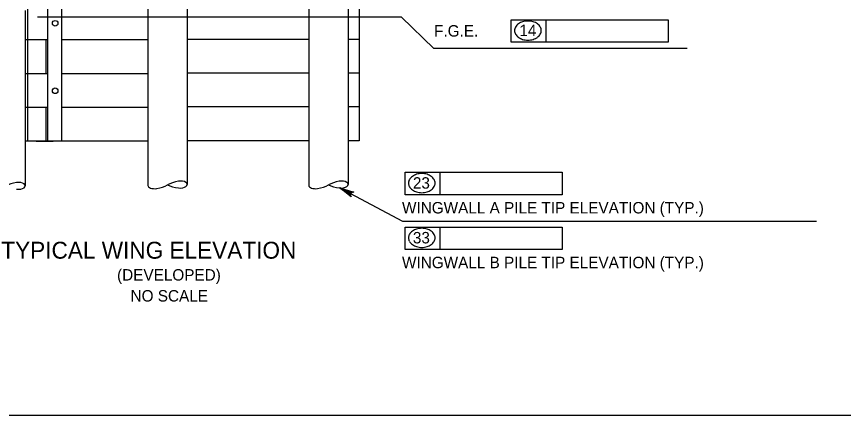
# Model space of a CAD drawing. Extents: x 638304 to 640306, y 296653 to 298435.
# Drawn here: x 638840 to 639056.8, y 297262.5 to 297367 of the extents above; entities that cross this region are included whole.
import ezdxf

# ---------------------------------------------------------------- set-up
doc = ezdxf.new("R2010")
doc.units = 0
for name, color, linetype in [('2', 7, 'Continuous'), ('5', 7, 'Continuous'), ('Level 4', 7, 'Continuous'), ('Level 5', 7, 'Continuous')]:
    doc.layers.add(name, color=color, linetype=linetype)

msp = doc.modelspace()

# ---------------------------------------------------------------- linework, layer by layer
at = {"layer": '2'}
msp.add_line((639261.46, 297262.46), (638475.46, 297262.46), dxfattribs=at)
at = {"layer": 'Level 4'}
for p, q in [((638842.93, 297413.92), (638842.93, 297334.35)), ((638926.95, 297395.53), (638926.95, 297323.03)), ((638929.9, 297396.36), (638929.9, 297334.47)), ((638916.63, 297392.09), (638916.63, 297322.76)), ((638884.77, 297381.85), (638884.77, 297323.03)), ((638874.45, 297377.11), (638874.45, 297322.76)), ((638851.9, 297334.35), (638851.9, 297371.26)), ((638848.27, 297334.35), (638848.27, 297370.09)), ((638842.32, 297368.59), (638842.32, 297322.64)), ((638848.27, 297360.87), (638842.32, 297360.87)), ((638847.75, 297360.87), (638847.75, 297352.03)), ((638874.45, 297360.87), (638851.9, 297360.87)), ((638916.63, 297360.99), (638884.77, 297360.99)), ((638929.9, 297360.99), (638926.95, 297360.99)), ((638848.27, 297352.03), (638842.32, 297352.03)), ((638874.45, 297352.03), (638851.9, 297352.03)), ((638916.63, 297352.15), (638884.77, 297352.15)), ((638929.9, 297352.15), (638926.95, 297352.15)), ((638848.27, 297343.19), (638842.32, 297343.19)), ((638847.75, 297343.19), (638847.75, 297334.35)), ((638874.45, 297343.19), (638851.9, 297343.19)), ((638916.63, 297343.31), (638884.77, 297343.31)), ((638929.9, 297343.31), (638926.95, 297343.31)), ((638916.63, 297334.47), (638884.77, 297334.47)), ((638929.9, 297334.47), (638926.95, 297334.47)), ((638874.45, 297334.35), (638842.32, 297334.35)), ((638845.2, 297334.35), (638849.62, 297334.35))]:
    msp.add_line(p, q, dxfattribs=at)
for centre in [(638850.16, 297365.24), (638850.16, 297347.56)]:
    msp.add_circle(centre, 0.737, dxfattribs=at)
for centre, major_axis, start_param, end_param in [((638840.5, 297322.64), (1.83, 0), 4.455588, 8.110783), ((638884.84, 297320.45), (7.29, 0.2), 1.89032, 2.356194), ((638882.94, 297322.98), (1.83, 0.05), 4.455588, 8.110783), ((638927.02, 297320.45), (7.29, 0.2), 1.89032, 2.356194), ((638925.12, 297322.98), (1.83, 0.05), 4.455588, 8.110783), ((638842.32, 297320.06), (7.29, 0), 1.89032, 2.356194), ((638876.28, 297322.81), (-1.83, -0.05), 0, 1.827597), ((638874.39, 297325.33), (-7.29, -0.2), 1.89032, 2.356194), ((638884.7, 297325.61), (7.29, 0.2), 3.926991, 4.392865), ((638918.46, 297322.81), (-1.83, -0.05), 0, 1.827597), ((638916.57, 297325.33), (-7.29, -0.2), 1.89032, 2.356194), ((638926.88, 297325.61), (7.29, 0.2), 3.926991, 4.392865)]:
    msp.add_ellipse(centre, major_axis=major_axis, ratio=0.5, start_param=start_param, end_param=end_param, dxfattribs=at)
at = {"layer": 'Level 5'}
for p, q in [((638940.93, 297366.83), (638845.53, 297366.83)), ((638940.93, 297366.83), (638949.43, 297358.64)), ((638969.73, 297366.17), (639010.86, 297366.17)), ((638969.73, 297360.28), (638969.73, 297366.17)), ((638978.88, 297360.28), (638978.88, 297366.17)), ((639010.86, 297366.17), (639010.86, 297360.28)), ((639015.81, 297358.64), (638949.43, 297358.64)), ((639010.86, 297360.28), (638969.73, 297360.28)), ((638941.91, 297326.2), (638983.04, 297326.2)), ((638941.91, 297320.3), (638941.91, 297326.2)), ((638951.06, 297320.3), (638951.06, 297326.2)), ((638983.04, 297326.2), (638983.04, 297320.3)), ((638924.83, 297322.16), (638941.18, 297313.38)), ((638983.04, 297320.3), (638941.91, 297320.3)), ((638941.18, 297313.38), (639049.77, 297313.38)), ((638941.91, 297311.85), (638983.04, 297311.85)), ((638941.91, 297305.95), (638941.91, 297311.85)), ((638951.06, 297305.95), (638951.06, 297311.85)), ((638983.04, 297311.85), (638983.04, 297305.95)), ((638983.04, 297305.95), (638941.91, 297305.95))]:
    msp.add_line(p, q, dxfattribs=at)
msp.add_lwpolyline([(638924.83, 297322.16), (638928.44, 297321.02), (638928.09, 297320.98), (638927.84, 297320.83), (638927.69, 297320.63), (638927.61, 297320.39), (638927.62, 297320.1), (638927.78, 297319.78), (638924.83, 297322.16), (638927.62, 297320.1), (638927.61, 297320.39), (638924.83, 297322.16), (638927.69, 297320.63), (638927.84, 297320.83), (638924.83, 297322.16), (638928.09, 297320.98)], dxfattribs=at)
for centre, radius, start, end in [((638973.23, 297362.87), 2.75, 125.6316, 149.9767), ((638973.75, 297362.14), 3.65, 106.5358, 125.6316), ((638974.1, 297360.98), 4.86, 90, 106.5358), ((638974.1, 297360.98), 4.86, 73.4642, 90), ((638974.44, 297362.14), 3.65, 54.3684, 73.4642), ((638974.97, 297362.87), 2.75, 30.0233, 54.3684), ((638972.42, 297363.33), 1.82, 149.9767, 180), ((638972.42, 297363.33), 1.82, 180, 210.0233), ((638975.77, 297363.33), 1.82, 0, 30.0233), ((638975.77, 297363.33), 1.82, 329.9767, 0), ((638973.23, 297363.8), 2.75, 210.0233, 234.3684), ((638973.75, 297364.53), 3.65, 234.3684, 253.4642), ((638974.1, 297365.69), 4.86, 253.4642, 270), ((638974.1, 297365.69), 4.86, 270, 286.5358), ((638974.44, 297364.53), 3.65, 286.5358, 305.6316), ((638974.97, 297363.8), 2.75, 305.6316, 329.9767), ((638946.27, 297321), 4.86, 90, 106.5358), ((638946.27, 297321), 4.86, 73.4642, 90), ((638944.6, 297323.36), 1.82, 149.9767, 180), ((638945.4, 297322.89), 2.75, 125.6316, 149.9767), ((638945.93, 297322.16), 3.65, 106.5358, 125.6316), ((638946.62, 297322.16), 3.65, 54.3684, 73.4642), ((638947.14, 297322.89), 2.75, 30.0233, 54.3684), ((638947.95, 297323.36), 1.82, 0, 30.0233), ((638944.6, 297323.36), 1.82, 180, 210.0233), ((638945.4, 297323.82), 2.75, 210.0233, 234.3684), ((638945.93, 297324.56), 3.65, 234.3684, 253.4642), ((638946.62, 297324.56), 3.65, 286.5358, 305.6316), ((638947.14, 297323.82), 2.75, 305.6316, 329.9767), ((638947.95, 297323.36), 1.82, 329.9767, 0), ((638946.27, 297325.71), 4.86, 253.4642, 270), ((638946.27, 297325.71), 4.86, 270, 286.5358), ((638945.4, 297308.54), 2.75, 125.6316, 149.9767), ((638945.93, 297307.81), 3.65, 106.5358, 125.6316), ((638946.27, 297306.65), 4.86, 90, 106.5358), ((638946.27, 297306.65), 4.86, 73.4642, 90), ((638946.62, 297307.81), 3.65, 54.3684, 73.4642), ((638947.14, 297308.54), 2.75, 30.0233, 54.3684), ((638944.6, 297309.01), 1.82, 149.9767, 180), ((638944.6, 297309.01), 1.82, 180, 210.0233), ((638947.95, 297309.01), 1.82, 0, 30.0233), ((638947.95, 297309.01), 1.82, 329.9767, 0), ((638945.4, 297309.47), 2.75, 210.0233, 234.3684), ((638945.93, 297310.2), 3.65, 234.3684, 253.4642), ((638946.27, 297311.36), 4.86, 253.4642, 270), ((638946.27, 297311.36), 4.86, 270, 286.5358), ((638946.62, 297310.2), 3.65, 286.5358, 305.6316), ((638947.14, 297309.47), 2.75, 305.6316, 329.9767)]:
    msp.add_arc(centre, radius, start, end, dxfattribs=at)

# ---------------------------------------------------------------- texts
at = {"layer": '5'}
for s, height, p in [('TYPICAL WING ELEVATION', 4.4294, (638836.04, 297303.55)), ('(DEVELOPED)', 3.0001, (638866.39, 297297.81)), ('NO SCALE', 3, (638869.93, 297292.31))]:
    msp.add_text(s, height=height, dxfattribs=at).set_placement(p)
at = {"layer": 'Level 5'}
for s, height, p in [('F.G.E.', 3, (638949.5, 297361.76)), ('14', 3, (638971.85, 297361.88)), ('23', 3, (638943.94, 297321.9)), ('WINGWALL A PILE TIP ELEVATION (TYP.)', 3.0001, (638941.09, 297315.4)), ('33', 3, (638943.94, 297307.55)), ('WINGWALL B PILE TIP ELEVATION (TYP.)', 3.0001, (638941.09, 297301.05))]:
    msp.add_text(s, height=height, dxfattribs=at).set_placement(p)

doc.saveas('drawing.dxf')
